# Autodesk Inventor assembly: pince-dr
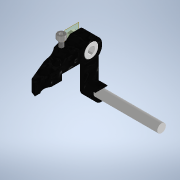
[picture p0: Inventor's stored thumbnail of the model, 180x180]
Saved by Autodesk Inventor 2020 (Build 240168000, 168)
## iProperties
Created: 2023-10
Part Number: pince-dr
Document SubType Name: Assembly
Designer: bruno
Author: bruno
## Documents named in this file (6)
- C:\Users\bruno\Documents\1-Cours-2023-24\Maquettes-Inventor\Pince-robot-Dobot\HS422\pince-dr.iam
- C:\Users\bruno\Documents\1-Cours-2023-24\Maquettes-Inventor\Pince-robot-Dobot\pince-d.ipt
- C:\Users\bruno\Documents\1-Cours-2023-24\Maquettes-Inventor\Pince-robot-Dobot\Tige-verin.ipt
- C:\Users\bruno\Documents\1-Cours-2023-24\Maquettes-Inventor\Pince-robot-Dobot\Douille.ipt
- C:\Users\bruno\Documents\Inventor\Content Center Files\R2020\fr-FR\KS B 1003\KS B 1003 - M 2 x 5.ipt
- C:\Users\bruno\Documents\Inventor\Content Center Files\R2020\fr-FR\KS B 1003\KS B 1003 - M 3 x 10.ipt
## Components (5 placed, 5 different names)
1. pince-d:1 — Placage:1, Affleurement:1, Placage:2, Placage:3, Placage:4, Logement:1, Placage:5, Placage:6
2. Tige-verin:1 — Placage:1, Placage:3, Placage:4
3. Douille:1 — Affleurement:1, Placage:2
4. KS B 1003 - Métrique M 2 x 5:1 — Logement:1
5. KS B 1003 - Métrique M 3 x 10:1 — Placage:5, Placage:6
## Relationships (8: Mate 6, Flush 1, Insert 1)
- Placage:1 [Mate]: pince-d:1 ↔ Tige-verin:1
- Affleurement:1 [Flush]: pince-d:1 ↔ Douille:1
- Placage:2 [Mate]: pince-d:1 ↔ Douille:1
- Placage:3 [Mate]: pince-d:1 ↔ Tige-verin:1
- Placage:4 [Mate]: pince-d:1 ↔ Tige-verin:1
- Logement:1 [Insert]: pince-d:1 ↔ KS B 1003 - Métrique M 2 x 5:1
- Placage:5 [Mate]: pince-d:1 ↔ KS B 1003 - Métrique M 3 x 10:1
- Placage:6 [Mate]: pince-d:1 ↔ KS B 1003 - Métrique M 3 x 10:1
